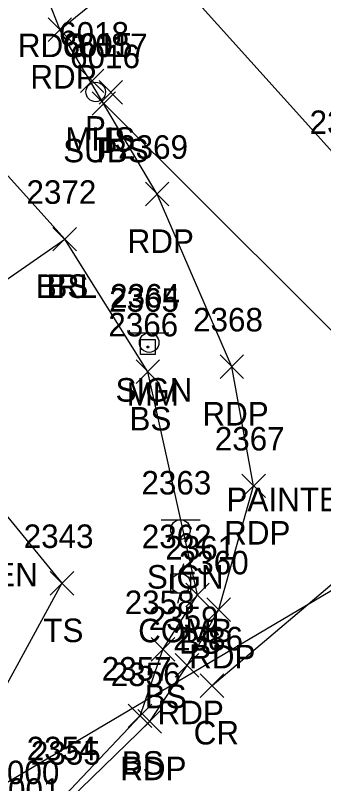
# Model space of a CAD drawing. Extents: x 1653135 to 1655489, y 602711 to 605684.
# Drawn here: x 1653631.2 to 1653657.5, y 605194.6 to 605259.9 of the extents above; entities that cross this region are included whole.
import ezdxf

# ---------------------------------------------------------------- set-up
doc = ezdxf.new("R2010")
doc.units = 0
for name, color, linetype in [('D_A', 7, 'Continuous'), ('D_I', 7, 'Continuous'), ('D_TIC', 7, 'Continuous'), ('L_A', 7, 'Continuous'), ('L_I', 7, 'Continuous'), ('L_TIC', 7, 'Continuous'), ('LABL', 7, 'Continuous'), ('LELB', 7, 'Continuous'), ('P_A', 7, 'Continuous'), ('P_I', 7, 'Continuous'), ('P_TIC', 7, 'Continuous'), ('PET', 7, 'Continuous'), ('PEU', 7, 'Continuous'), ('PRC', 7, 'Continuous'), ('S_A', 7, 'Continuous'), ('S_I', 7, 'Continuous'), ('SRM', 7, 'Continuous'), ('SSGN', 7, 'Continuous'), ('U_A', 7, 'Continuous'), ('U_C', 7, 'Continuous'), ('U_I', 7, 'Continuous'), ('U_TIC', 7, 'Continuous'), ('UP', 7, 'Continuous'), ('USA', 7, 'Continuous'), ('USMH', 7, 'Continuous')]:
    doc.layers.add(name, color=color, linetype=linetype)

msp = doc.modelspace()

# ---------------------------------------------------------------- linework, layer by layer
at = {"layer": 'D_TIC'}
for points in [[(1653636.776, 605253.36), (1653638.776, 605255.36)], [(1653638.776, 605253.36), (1653636.776, 605255.36)], [(1653636.776, 605253.36), (1653638.776, 605255.36)], [(1653638.776, 605253.36), (1653636.776, 605255.36)], [(1653638.366, 605252.383), (1653640.366, 605254.383)], [(1653640.366, 605252.383), (1653638.366, 605254.383)], [(1653638.366, 605252.383), (1653640.366, 605254.383)], [(1653640.366, 605252.383), (1653638.366, 605254.383)], [(1653637.765, 605251.439), (1653639.765, 605253.439)], [(1653639.765, 605251.439), (1653637.765, 605253.439)]]:
    msp.add_lwpolyline(points, dxfattribs=at)
at = {"layer": 'L_TIC'}
for points in [[(1653634.435, 605239.907), (1653636.435, 605241.907)], [(1653636.435, 605239.907), (1653634.435, 605241.907)], [(1653634.435, 605239.907), (1653636.435, 605241.907)], [(1653636.435, 605239.907), (1653634.435, 605241.907)], [(1653634.435, 605239.907), (1653636.435, 605241.907)], [(1653636.435, 605239.907), (1653634.435, 605241.907)], [(1653634.435, 605239.907), (1653636.435, 605241.907)], [(1653636.435, 605239.907), (1653634.435, 605241.907)], [(1653641.505, 605228.637), (1653643.505, 605230.637)], [(1653643.505, 605228.637), (1653641.505, 605230.637)], [(1653641.505, 605228.637), (1653643.505, 605230.637)], [(1653643.505, 605228.637), (1653641.505, 605230.637)], [(1653634.198, 605210.648), (1653636.198, 605212.648)], [(1653636.198, 605210.648), (1653634.198, 605212.648)], [(1653634.198, 605210.648), (1653636.198, 605212.648)], [(1653636.198, 605210.648), (1653634.198, 605212.648)], [(1653645.734, 605209.66), (1653647.734, 605211.66)], [(1653647.734, 605209.66), (1653645.734, 605211.66)], [(1653645.734, 605209.66), (1653647.734, 605211.66)], [(1653647.734, 605209.66), (1653645.734, 605211.66)], [(1653642.8, 605205.03), (1653644.8, 605207.03)], [(1653644.8, 605205.03), (1653642.8, 605207.03)], [(1653642.8, 605205.03), (1653644.8, 605207.03)], [(1653644.8, 605205.03), (1653642.8, 605207.03)], [(1653640.847, 605199.375), (1653642.847, 605201.375)], [(1653642.847, 605199.375), (1653640.847, 605201.375)], [(1653640.847, 605199.375), (1653642.847, 605201.375)], [(1653642.847, 605199.375), (1653640.847, 605201.375)]]:
    msp.add_lwpolyline(points, dxfattribs=at)
at = {"layer": 'LABL'}
msp.add_lwpolyline([(1653607.522, 605245.008), (1653619.975, 605230.203), (1653635.435, 605240.907), (1653624.548, 605252.971)], dxfattribs=at)
at = {"layer": 'LELB'}
for points in [[(1653615.016, 605180.668), (1653625.679, 605186.615), (1653635.454, 605193.599), (1653641.847, 605200.375), (1653643.8, 605206.03), (1653646.734, 605210.66), (1653642.505, 605229.637), (1653635.435, 605240.907)], [(1653619.975, 605230.203), (1653635.198, 605211.648), (1653628.033, 605198.608), (1653617.111, 605185.649), (1653607.046, 605179.572), (1653604.168, 605184)]]:
    msp.add_lwpolyline(points, dxfattribs=at)
at = {"layer": 'P_TIC'}
for points in [[(1653634.016, 605257.706), (1653636.016, 605259.706)], [(1653636.016, 605257.706), (1653634.016, 605259.706)], [(1653634.016, 605257.706), (1653636.016, 605259.706)], [(1653636.016, 605257.706), (1653634.016, 605259.706)], [(1653642.298, 605243.735), (1653644.298, 605245.735)], [(1653644.298, 605243.735), (1653642.298, 605245.735)], [(1653642.298, 605243.735), (1653644.298, 605245.735)], [(1653644.298, 605243.735), (1653642.298, 605245.735)], [(1653648.666, 605229.059), (1653650.666, 605231.059)], [(1653650.666, 605229.059), (1653648.666, 605231.059)], [(1653648.666, 605229.059), (1653650.666, 605231.059)], [(1653650.666, 605229.059), (1653648.666, 605231.059)], [(1653650.517, 605218.938), (1653652.517, 605220.938)], [(1653652.517, 605218.938), (1653650.517, 605220.938)], [(1653650.517, 605218.938), (1653652.517, 605220.938)], [(1653652.517, 605218.938), (1653650.517, 605220.938)], [(1653647.542, 605208.408), (1653649.542, 605210.408)], [(1653649.542, 605208.408), (1653647.542, 605210.408)], [(1653647.542, 605208.408), (1653649.542, 605210.408)], [(1653649.542, 605208.408), (1653647.542, 605210.408)], [(1653644.849, 605203.668), (1653646.849, 605205.668)], [(1653646.849, 605203.668), (1653644.849, 605205.668)], [(1653644.849, 605203.668), (1653646.849, 605205.668)], [(1653646.849, 605203.668), (1653644.849, 605205.668)], [(1653646.978, 605201.943), (1653648.978, 605203.943)], [(1653648.978, 605201.943), (1653646.978, 605203.943)], [(1653646.978, 605201.943), (1653648.978, 605203.943)], [(1653648.978, 605201.943), (1653646.978, 605203.943)], [(1653641.668, 605198.906), (1653643.668, 605200.906)], [(1653643.668, 605198.906), (1653641.668, 605200.906)], [(1653641.668, 605198.906), (1653643.668, 605200.906)], [(1653643.668, 605198.906), (1653641.668, 605200.906)]]:
    msp.add_lwpolyline(points, dxfattribs=at)
at = {"layer": 'PET'}
msp.add_lwpolyline([(1653578.163, 605163.394), (1653590, 605168.27), (1653605.168, 605176.583), (1653615.016, 605180.668), (1653625.927, 605186.038), (1653635.808, 605193.227), (1653642.668, 605199.906), (1653645.849, 605204.668), (1653648.542, 605209.408), (1653651.517, 605219.938), (1653649.666, 605230.059), (1653643.298, 605244.735), (1653635.016, 605258.706), (1653643.013, 605265.182), (1653654.524, 605279.776), (1653665.481, 605274.477)], dxfattribs=at)
at = {"layer": 'PEU'}
msp.add_lwpolyline([(1653633.955, 605261.378), (1653635.016, 605258.706)], dxfattribs=at)
at = {"layer": 'PRC'}
for points in [[(1653726.648, 605268.269), (1653711.087, 605253.466), (1653692.662, 605235.598), (1653674.715, 605225.537), (1653647.978, 605202.943)], [(1653643.013, 605265.182), (1653659.542, 605246.842), (1653674.715, 605225.537)]]:
    msp.add_lwpolyline(points, dxfattribs=at)
at = {"layer": 'SRM'}
msp.add_lwpolyline([(1653641.895, 605232.362), (1653643.145, 605232.362), (1653643.145, 605231.112), (1653641.895, 605231.112)], close=True, dxfattribs=at)
msp.add_circle((1653642.52, 605231.737), 0.0833, dxfattribs=at)
at = {"layer": 'SSGN'}
for p, q in [((1653640.977, 605232.945), (1653644.31, 605232.945)), ((1653642.624, 605232.112), (1653642.624, 605232.112)), ((1653643.64, 605217.05), (1653646.974, 605217.05)), ((1653645.287, 605216.216), (1653645.287, 605216.216))]:
    msp.add_line(p, q, dxfattribs=at)
for centre in [(1653642.624, 605232.112), (1653645.287, 605216.216)]:
    msp.add_circle(centre, 0.833, dxfattribs=at)
at = {"layer": 'U_TIC'}
for points in [[(1653637.765, 605251.439), (1653639.765, 605253.439)], [(1653639.765, 605251.439), (1653637.765, 605253.439)]]:
    msp.add_lwpolyline(points, dxfattribs=at)
at = {"layer": 'UP'}
for p, q in [((1653645.551, 605213.298), (1653645.301, 605212.465)), ((1653644.468, 605210.798), (1653644.468, 605212.465)), ((1653644.468, 605212.465), (1653646.135, 605212.465)), ((1653646.135, 605212.465), (1653646.135, 605210.798)), ((1653645.301, 605211.631), (1653645.301, 605211.631)), ((1653646.135, 605210.798), (1653644.468, 605210.798)), ((1653645.051, 605209.965), (1653645.301, 605210.798))]:
    msp.add_line(p, q, dxfattribs=at)
msp.add_circle((1653645.301, 605211.631), 0.833, dxfattribs=at)
at = {"layer": 'USA'}
for points in [[(1653664.528, 605226.779), (1653638.765, 605252.439)], [(1653424.094, 605072.763), (1653667.014, 605216.275)]]:
    msp.add_lwpolyline(points, dxfattribs=at)
at = {"layer": 'USMH'}
for p, q in [((1653638.071, 605253.417), (1653638.071, 605253.417)), ((1653638.904, 605253.417), (1653638.904, 605253.417))]:
    msp.add_line(p, q, dxfattribs=at)
msp.add_circle((1653638.071, 605253.417), 0.833, dxfattribs=at)

# ---------------------------------------------------------------- texts
at = {"layer": 'D_A'}
for p in [(1653637.154, 605249.36), (1653637.154, 605249.36), (1653638.744, 605248.383), (1653638.744, 605248.383), (1653638.143, 605247.439)]:
    msp.add_text('P', height=2, dxfattribs=at).set_placement(p)
at = {"layer": 'D_I'}
for s, p in [('6018', (1653634.957, 605257.36)), ('6018', (1653634.957, 605257.36)), ('6017', (1653636.548, 605256.383)), ('6017', (1653636.548, 605256.383)), ('6016', (1653635.891, 605255.439))]:
    msp.add_text(s, height=2, dxfattribs=at).set_placement(p)
at = {"layer": 'L_A'}
for s, p in [('BRL', (1653632.978, 605235.907)), ('BRL', (1653632.978, 605235.907)), ('BS', (1653633.876, 605235.907)), ('BS', (1653633.876, 605235.907)), ('BS', (1653640.946, 605224.637)), ('BS', (1653640.946, 605224.637)), ('GARDEN', (1653621.7, 605211.385)), ('GARDEN', (1653621.7, 605211.385)), ('TS', (1653633.607, 605206.648)), ('TS', (1653633.607, 605206.648)), ('BS', (1653645.175, 605205.66)), ('BS', (1653645.175, 605205.66)), ('BS', (1653642.241, 605201.03)), ('BS', (1653642.241, 605201.03)), ('BS', (1653640.288, 605195.375)), ('BS', (1653640.288, 605195.375))]:
    msp.add_text(s, height=2, dxfattribs=at).set_placement(p)
at = {"layer": 'L_I'}
for s, p in [('2372', (1653632.175, 605243.907)), ('2372', (1653632.175, 605243.907)), ('2372', (1653632.175, 605243.907)), ('2372', (1653632.175, 605243.907)), ('2366', (1653639.143, 605232.637)), ('2366', (1653639.143, 605232.637)), ('2343', (1653631.938, 605214.648)), ('2343', (1653631.938, 605214.648)), ('2361', (1653643.993, 605213.66)), ('2361', (1653643.993, 605213.66)), ('2358', (1653640.54, 605209.03)), ('2358', (1653640.54, 605209.03)), ('2357', (1653638.587, 605203.375)), ('2357', (1653638.587, 605203.375)), ('2354', (1653632.194, 605196.599)), ('2354', (1653632.194, 605196.599))]:
    msp.add_text(s, height=2, dxfattribs=at).set_placement(p)
at = {"layer": 'P_A'}
for s, p in [('RDG', (1653631.443, 605256.378)), ('RDG', (1653631.443, 605256.378)), ('RDP', (1653632.504, 605253.706)), ('RDP', (1653632.504, 605253.706)), ('RDP', (1653640.786, 605239.735)), ('RDP', (1653640.786, 605239.735)), ('RDP', (1653647.154, 605225.059)), ('RDP', (1653647.154, 605225.059)), ('RDP', (1653649.006, 605214.938)), ('RDP', (1653649.006, 605214.938)), ('RDP', (1653646.03, 605204.408)), ('RDP', (1653646.03, 605204.408)), ('RDP', (1653643.337, 605199.668)), ('RDP', (1653643.337, 605199.668)), ('CR', (1653646.411, 605197.943)), ('CR', (1653646.411, 605197.943)), ('RDP', (1653640.156, 605194.906)), ('RDP', (1653640.156, 605194.906))]:
    msp.add_text(s, height=2, dxfattribs=at).set_placement(p)
at = {"layer": 'P_I'}
for s, p in [('2384', (1653656.282, 605249.842)), ('2384', (1653656.282, 605249.842)), ('2369', (1653639.983, 605247.735)), ('2369', (1653639.983, 605247.735)), ('2368', (1653646.359, 605233.059)), ('2368', (1653646.359, 605233.059)), ('2367', (1653648.21, 605222.938)), ('2367', (1653648.21, 605222.938)), ('2360', (1653645.149, 605212.408)), ('2360', (1653645.149, 605212.408)), ('2359', (1653642.581, 605207.668)), ('2359', (1653642.581, 605207.668)), ('2386', (1653644.663, 605205.943)), ('2386', (1653644.663, 605205.943)), ('2356', (1653639.353, 605202.906)), ('2356', (1653639.353, 605202.906)), ('2355', (1653632.548, 605196.227)), ('2355', (1653632.548, 605196.227))]:
    msp.add_text(s, height=2, dxfattribs=at).set_placement(p)
at = {"layer": 'S_A'}
for s, p in [('SIGN', (1653639.762, 605227.092)), ('MM', (1653640.709, 605226.737)), ('SIGN', (1653642.425, 605211.196))]:
    msp.add_text(s, height=2, dxfattribs=at).set_placement(p)
at = {"layer": 'S_I'}
for s, p in [('2365', (1653639.213, 605234.737)), ('2364', (1653639.297, 605235.092)), ('2363', (1653641.96, 605219.196))]:
    msp.add_text(s, height=2, dxfattribs=at).set_placement(p)
at = {"layer": 'U_A'}
for s, p in [('MHS', (1653635.489, 605248.417)), ('SUBS', (1653635.301, 605247.439)), ('COMB', (1653641.687, 605206.631))]:
    msp.add_text(s, height=2, dxfattribs=at).set_placement(p)
at = {"layer": 'U_C'}
msp.add_text('PAINTED GREEN LINE', height=2, dxfattribs=at).set_placement((1653649.206, 605217.779))
msp.add_text('PAINTED GREEN LINE', height=2, dxfattribs=at).set_placement((1653649.206, 605217.779))
msp.add_text('PAINTED GREEN LINE', height=2, dxfattribs=at).set_placement((1653649.206, 605217.779))
at = {"layer": 'U_I'}
for s, p in [('6015', (1653635.252, 605256.417)), ('6016', (1653635.891, 605255.439)), ('2362', (1653641.994, 605214.631)), ('4000', (1653629.028, 605194.569)), ('4001', (1653629.118, 605193.067))]:
    msp.add_text(s, height=2, dxfattribs=at).set_placement(p)

doc.saveas('drawing.dxf')
